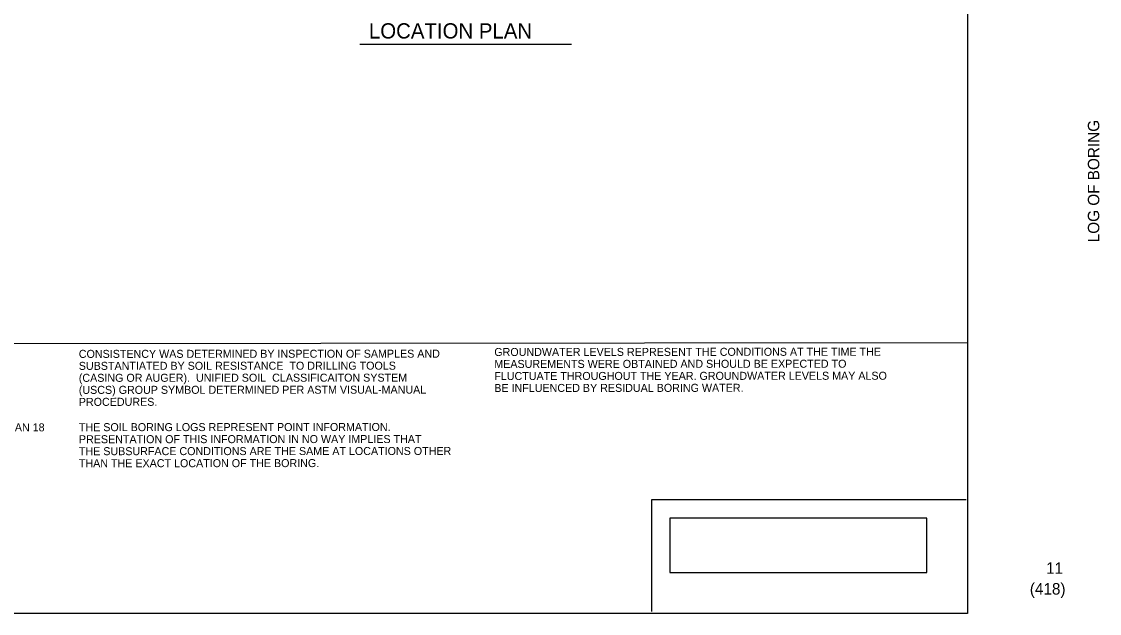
# Model space of a CAD drawing. Extents: x 19007.1 to 19038.2, y 21497.8 to 21516.9.
# Drawn here: x 19024.02 to 19038.15, y 21497.77 to 21505.53 of the extents above; entities that cross this region are included whole.
import ezdxf

# ---------------------------------------------------------------- set-up
doc = ezdxf.new("R2010")
doc.units = 0
for name, color, linetype in [('BORDER', 7, 'Continuous'), ('C-ANNO-TEXT', 7, 'Continuous'), ('G-ANNO-TTLB', 7, 'Continuous'), ('Level 1', 7, 'Continuous'), ('TYPICAL_TEXT_DIMEN_PR', 7, 'Continuous')]:
    doc.layers.add(name, color=color, linetype=linetype)

msp = doc.modelspace()

# ---------------------------------------------------------------- linework, layer by layer
at = {"layer": 'C-ANNO-TEXT'}
msp.add_line((19028.458, 21505.231), (19031.234, 21505.231), dxfattribs=at)
at = {"layer": 'G-ANNO-TTLB'}
for p, q in [((19036.407, 21499.256), (19032.28, 21499.256)), ((19032.28, 21499.256), (19032.28, 21497.791))]:
    msp.add_line(p, q, dxfattribs=at)
msp.add_lwpolyline([(19036.423, 21497.766), (19007.08, 21497.766), (19007.08, 21516.881), (19036.423, 21516.881)], close=True, dxfattribs=at)
at = {"layer": 'Level 1'}
msp.add_line((19007.08, 21501.296), (19036.429, 21501.317), dxfattribs=at)
msp.add_line((19007.08, 21501.296), (19036.429, 21501.317), dxfattribs=at)
at = {"layer": 'TYPICAL_TEXT_DIMEN_PR'}
msp.add_lwpolyline([(19032.522, 21498.304), (19035.891, 21498.304), (19035.891, 21499.017), (19032.522, 21499.017)], close=True, dxfattribs=at)

# ---------------------------------------------------------------- texts
at = {"layer": 'BORDER'}
for s, p in [('CONSISTENCY WAS DETERMINED BY INSPECTION OF SAMPLES AND ', (19024.772, 21501.117)), ('GROUNDWATER LEVELS REPRESENT THE CONDITIONS AT THE TIME THE ', (19030.22, 21501.142)), ('SUBSTANTIATED BY SOIL RESISTANCE  TO DRILLING TOOLS ', (19024.772, 21500.96)), ('MEASUREMENTS WERE OBTAINED AND SHOULD BE EXPECTED TO ', (19030.22, 21500.985)), ('FLUCTUATE THROUGHOUT THE YEAR. GROUNDWATER LEVELS MAY ALSO ', (19030.22, 21500.827)), ('(CASING OR AUGER).  UNIFIED SOIL  CLASSIFICAITON SYSTEM ', (19024.772, 21500.803)), ('(USCS) GROUP SYMBOL DETERMINED PER ASTM VISUAL-MANUAL ', (19024.772, 21500.645)), ('BE INFLUENCED BY RESIDUAL BORING WATER. ', (19030.22, 21500.67)), ('PROCEDURES.', (19024.772, 21500.488)), ('WHERE THE SAMPLER IS DRIVEN DISTANCES OTHER THAN 18 ', (19020.041, 21500.151)), ('THE SOIL BORING LOGS REPRESENT POINT INFORMATION. ', (19024.773, 21500.156)), ('PRESENTATION OF THIS INFORMATION IN NO WAY IMPLIES THAT ', (19024.773, 21499.998)), ('THE SUBSURFACE CONDITIONS ARE THE SAME AT LOCATIONS OTHER ', (19024.773, 21499.841)), ('THAN THE EXACT LOCATION OF THE BORING.', (19024.773, 21499.683))]:
    msp.add_text(s, height=0.10498, rotation=0.0399, dxfattribs=at).set_placement(p)
at = {"layer": 'C-ANNO-TEXT'}
msp.add_text('LOCATION PLAN', height=0.2, dxfattribs=at).set_placement((19028.576, 21505.305))
at = {"layer": 'G-ANNO-TTLB'}
msp.add_text('LOG OF BORING', height=0.15, rotation=90, dxfattribs=at).set_placement((19038.153, 21502.633))
for s, p in [('11', (19037.455, 21498.286)), ('(418)', (19037.242, 21498.014))]:
    msp.add_text(s, height=0.15, dxfattribs=at).set_placement(p)

doc.saveas('drawing.dxf')
